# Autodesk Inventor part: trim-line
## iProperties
Shininess: 64.0
Length Units: 11269
Angle Units: 11279
Time Units: 11290
Mass Units: 11283
Length Display Precision: 3
Angle Display Precision: 2
Compacted: True
Part Number: trim-line
Document SubType Name: Modeling
Created: 2003-08
Designer: Owner
Manufacturer: Standard
Standards Organization: Custom
Density: 0.0
Volumn: 0.0
Area: 0.0
PropertySet Name: Model Information
Control State: 0
Master: False
Checked Out: False
Author: Owner
